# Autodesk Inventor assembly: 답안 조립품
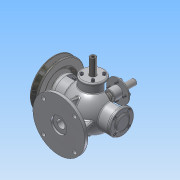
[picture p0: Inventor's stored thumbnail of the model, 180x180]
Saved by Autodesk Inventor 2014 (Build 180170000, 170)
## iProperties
Created: 2016-01
Part Number: 답안 조립품
Document SubType Name: Assembly
Designer: Administrator
Author: Administrator
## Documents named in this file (17)
- C:\Users\Administrator\Desktop\360108V1012\답안 조립품.iam
- C:\Users\Administrator\Desktop\360108V1012\본체.ipt
- C:\Users\Administrator\Desktop\360108V1012\본체커버.ipt
- C:\Users\Administrator\Desktop\360108V1012\축.ipt
- C:\Users\Administrator\Desktop\360108V1012\베어링- 6202.ipt
- C:\Users\Administrator\Desktop\360108V1012\앞커버.ipt
- C:\Users\Administrator\Desktop\360108V1012\뒤커버.ipt
- C:\Users\Administrator\Desktop\360108V1012\키-4x4.ipt
- C:\Users\Administrator\Desktop\360108V1012\오일실.ipt
- C:\Users\Administrator\Desktop\360108V1012\볼트 M4x0.7.ipt
- C:\Users\Administrator\Desktop\360108V1012\V-벨트풀리.ipt
- C:\Users\Administrator\Desktop\360108V1012\와셔 8x17.ipt
- C:\Users\Administrator\Desktop\360108V1012\너트-M8x1.ipt
- C:\Users\Administrator\Desktop\360108V1012\슬라이드 커버.ipt
- C:\Users\Administrator\Desktop\360108V1012\슬라이드.ipt
- C:\Users\Administrator\Desktop\360108V1012\가변스프링.ipt
- C:\Users\Administrator\Desktop\360108V1012\16-가변스프링.ipt
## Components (20 placed, 4 different names)
1. V-벨트풀리:1 — 플러쉬:1, 각도:2
2. M4x0.7x12:17
3. 가변스프링:1
4. 16-가변스프링:1
5. M4x0.7x12:2
6. M4x0.7x12:3
7. M4x0.7x12:4
8. M4x0.7x12:5
9. M4x0.7x12:1
10. M4x0.7x12:6
11. M4x0.7x12:7
12. M4x0.7x12:8
13. M4x0.7x12:9
14. M4x0.7x12:11
15. M4x0.7x12:12
16. M4x0.7x12:13
17. M4x0.7x12:10
18. M4x0.7x12:14
19. M4x0.7x12:15
20. M4x0.7x12:16
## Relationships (2: Flush 1, Angle 1)
- 플러쉬:1 [Flush]: V-벨트풀리:1
- 각도:2 [Angle]: V-벨트풀리:1
